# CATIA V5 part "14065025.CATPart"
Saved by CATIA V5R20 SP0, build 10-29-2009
Part number: 14065025
Definition: NONE
Nomenclature: 14065025
Source: Unknown
Description: 14065025
Bounding box of the stored display mesh (mm): x -12.5 to 50, y -46.5 to 36.6, z -36.6 to 36.6
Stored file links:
  C:\Users\Utente\Desktop\IO LAVORO\3D X SITO CF\X SITO\PLASTICA\RF2\14065025.CATPart
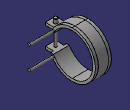
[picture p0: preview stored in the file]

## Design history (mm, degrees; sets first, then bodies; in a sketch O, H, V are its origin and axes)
Body1 "14065025" (main body)
  Solid1: solid without history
